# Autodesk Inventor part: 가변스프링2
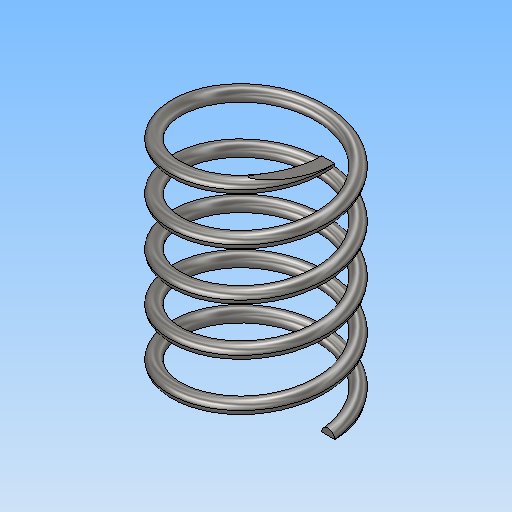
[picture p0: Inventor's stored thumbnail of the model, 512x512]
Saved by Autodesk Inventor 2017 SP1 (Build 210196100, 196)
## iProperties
Part Number: 가변스프링2
Material: 강철, 연강
Document SubType Name: Modeling
Designer: MRC
Density: 7.85 g/cm^3
Appearance: 반연마
Mass: 8.42324 g
Surface Area: 21.7217 cm^2
Volume: 1.07302 cm^3
Author: MRC
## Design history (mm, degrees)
sketch "스케치1"
  geometry: L1 (0, 0)-(0, 36.411); L2 (0, 36.411)-(11, 36.411); L3 (0, 0)-(11, 0); C1 r 1 at (11, 0)
  constraints: 6 end point, 2 horizontal, 1 centre point, 1 coincident, 1 vertical
  dimensions: "d0" = 36.4112 distance of L1.start L1.end (derived); "d1" = 11 distance of L1.end L2.end; "d2" = 22 diameter of L3.end L1; "d3" = 2 diameter of C1
feature "코일1" sketch "스케치1" pitch "d4" = 10; turns "d6" = 5; dims "d5" = 36.4112 (= d0), "d7" = 0, angle "d8" = 90 deg, angle "d9" = 90 deg, "d10" = 0, "d11" = 0
sketch "스케치2"
  geometry: L1 (36.411, 20)-(0, 20); L2 (0, 20)-(0, -20); L3 (0, -20)-(36.411, -20); L4 (36.411, -20)-(36.411, 20); 2 further points
  constraints: 8 end point, 2 parallel, 1 coincident, 1 horizontal, 1 midpoint, 1 perpendicular
  dimensions: "d12" = 36.4112 distance of L2.end L3.end (= d0); "d13" = 40 distance of L3.end L1.start
extrude "돌출1" sketch "스케치2" stored distance "d14" = 0; taper "d15" = 0 deg
node "솔리드1"
